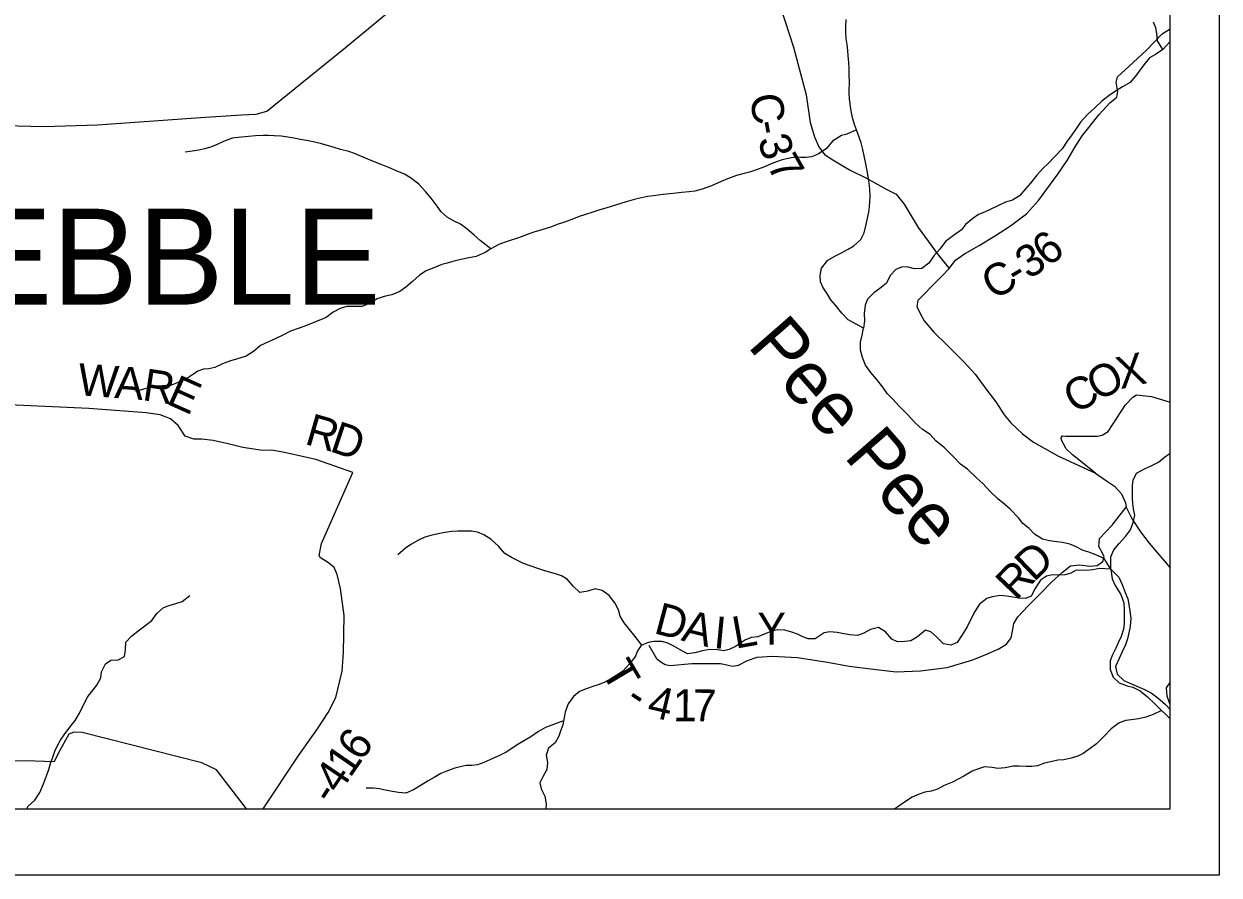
# Model space of a CAD drawing. Extents: x 0 to 34, y 0 to 22.
# Drawn here: x 6.965 to 9.087, y 13.882 to 15.393 of the extents above; entities that cross this region are included whole.
import ezdxf

# ---------------------------------------------------------------- set-up
doc = ezdxf.new("R2010")
doc.units = 0
for name, color, linetype in [('Default', 7, 'Continuous'), ('GM_X_County_Road', 7, 'Continuous'), ('GM_X_County_Road_Text', 7, 'Continuous'), ('GM_X_Major_River', 7, 'Continuous'), ('GM_X_Major_River_Text', 7, 'Continuous'), ('GM_X_Minor_Lake', 7, 'Continuous'), ('GM_X_Minor_River', 7, 'Continuous'), ('GM_X_Township_Road', 7, 'Continuous'), ('GM_X_Township_Road_Text', 7, 'Continuous'), ('GM_X_Township_Text', 7, 'Continuous'), ('SH_Cut_Line', 7, 'Continuous')]:
    doc.layers.add(name, color=color, linetype=linetype)

msp = doc.modelspace()

# ---------------------------------------------------------------- linework, layer by layer
at = {"layer": 'Default'}
msp.add_lwpolyline([(9.087, 13.8822), (2.1062, 13.8822), (2.1062, 20.9054), (9.087, 20.9054)], close=True, dxfattribs=at)
msp.add_lwpolyline([(4.485, 14), (9, 14), (9, 18.8941)], dxfattribs=at)
at = {"layer": 'GM_X_County_Road'}
for points in [[(8.3082, 15.4233), (8.3311, 15.3523), (8.3536, 15.2672), (8.361, 15.2182), (8.3686, 15.1927), (8.3765, 15.1749), (8.3863, 15.1616), (8.4011, 15.152), (8.4306, 15.1341), (8.4598, 15.1203), (8.4969, 15.0993), (8.5136, 15.091), (8.5276, 15.0734), (8.5529, 15.032), (8.5884, 14.9837), (8.6076, 14.959)], [(8.6076, 14.959), (8.6187, 14.9737), (8.6351, 14.9854), (8.6609, 15.0002), (8.6902, 15.0175), (8.7168, 15.0349), (8.7453, 15.0561), (8.7663, 15.0799), (8.8006, 15.1265), (8.817, 15.1508), (8.8315, 15.1754), (8.8437, 15.1947), (8.8741, 15.2326), (8.8928, 15.2531), (8.8993, 15.2587), (8.9057, 15.2636), (8.9073, 15.2739), (8.9062, 15.2796), (8.9043, 15.2902), (8.9066, 15.2993), (8.9268, 15.3175), (8.9584, 15.347), (8.9862, 15.3758), (9, 15.3849)], [(8.6076, 14.959), (8.5955, 14.9461), (8.5764, 14.9272), (8.5639, 14.9143), (8.5521, 14.9026), (8.5505, 14.8916), (8.5554, 14.8802), (8.5633, 14.8661), (8.5807, 14.8463), (8.6034, 14.8238), (8.6344, 14.7926), (8.6537, 14.7717), (8.6745, 14.7431), (8.6908, 14.7222), (8.7055, 14.6994), (8.7172, 14.6849), (8.738, 14.6655), (8.7577, 14.651), (8.8005, 14.6266), (8.8676, 14.5957), (8.8872, 14.5821), (8.9011, 14.5728), (8.9139, 14.5593), (8.9209, 14.5433), (8.922, 14.5357), (8.9325, 14.5139), (8.9473, 14.4914), (8.9629, 14.4716), (9, 14.4278)]]:
    msp.add_lwpolyline(points, dxfattribs=at)
at = {"layer": 'GM_X_Major_River'}
for points in [[(8.4556, 14.8532), (8.4283, 14.8683), (8.417, 14.8801), (8.4057, 14.8943), (8.3978, 14.9038), (8.3915, 14.9137), (8.3832, 14.9259), (8.3791, 14.9355), (8.3788, 14.9465), (8.3812, 14.9597), (8.3923, 14.9737), (8.4057, 14.9816), (8.4152, 14.9861), (8.4282, 14.9936), (8.4381, 14.9996), (8.4511, 15.0105), (8.4569, 15.0222), (8.46, 15.037), (8.4624, 15.0484), (8.4648, 15.059), (8.466, 15.0685), (8.4668, 15.078), (8.4673, 15.0875), (8.467, 15.1004), (8.4648, 15.1145), (8.463, 15.1259), (8.4612, 15.1354), (8.459, 15.1479), (8.4568, 15.1593), (8.4546, 15.1704), (8.4513, 15.1825), (8.448, 15.1924), (8.4431, 15.2054), (8.4398, 15.2149), (8.4364, 15.2248), (8.4342, 15.2354), (8.4324, 15.2468), (8.4306, 15.2605), (8.4303, 15.2719), (8.4305, 15.2917), (8.4302, 15.3019), (8.4299, 15.3141), (8.4296, 15.3251), (8.4286, 15.3365), (8.4275, 15.3464), (8.4265, 15.357), (8.425, 15.3677), (8.424, 15.3783), (8.424, 15.3889), (8.4245, 15.4011)], [(8.8949, 14.4256), (8.8827, 14.4441), (8.8684, 14.4506), (8.8559, 14.4556), (8.8456, 14.4587), (8.832, 14.4656), (8.8218, 14.4698), (8.8089, 14.4725), (8.7991, 14.4741), (8.7858, 14.4757), (8.7733, 14.4784), (8.7593, 14.4876), (8.7499, 14.4975), (8.7386, 14.5063), (8.731, 14.5162), (8.7163, 14.5318), (8.7065, 14.5402), (8.694, 14.5502), (8.6797, 14.5639), (8.6673, 14.5772), (8.6567, 14.5872), (8.6401, 14.6028), (8.6276, 14.612), (8.6152, 14.625), (8.5993, 14.641), (8.5838, 14.6532), (8.574, 14.6643), (8.5604, 14.6734), (8.5472, 14.6849), (8.5337, 14.7001), (8.5189, 14.7146), (8.5076, 14.7272), (8.4974, 14.7372), (8.4899, 14.7486), (8.4786, 14.7627), (8.4684, 14.7745), (8.459, 14.7878), (8.4538, 14.8012), (8.4501, 14.8141), (8.4501, 14.8281), (8.4532, 14.8407), (8.4556, 14.8532)], [(8.8949, 14.4256), (8.897, 14.4083), (8.9026, 14.3962), (8.9127, 14.3805), (8.9176, 14.3653), (8.9183, 14.3524), (8.9182, 14.3289), (8.9173, 14.319), (8.9131, 14.3061), (8.9077, 14.2947), (8.9035, 14.2853), (8.8978, 14.2731), (8.8935, 14.2625), (8.8935, 14.2473), (8.8987, 14.2336), (8.9096, 14.2237), (8.9236, 14.2183), (8.9339, 14.2156), (8.9471, 14.2095), (8.9599, 14.1988), (8.9724, 14.187), (8.9815, 14.1774), (8.9935, 14.166), (9, 14.1598)], [(8.8949, 14.4256), (8.9087, 14.4109), (8.9147, 14.3984), (8.9203, 14.3839), (8.9248, 14.3729), (8.9267, 14.3626), (8.9285, 14.3505), (8.93, 14.3383), (8.9291, 14.3235), (8.9268, 14.3121), (8.9241, 14.3019), (8.9206, 14.2913), (8.9149, 14.2784), (8.9095, 14.2666), (8.903, 14.2526), (8.9059, 14.2389), (8.918, 14.2279), (8.9316, 14.2217), (8.9449, 14.216), (8.9547, 14.2117), (8.9664, 14.2056), (8.9781, 14.1972), (8.9917, 14.185), (9, 14.1763)]]:
    msp.add_lwpolyline(points, dxfattribs=at)
at = {"layer": 'GM_X_Minor_Lake'}
msp.add_lwpolyline([(8.8949, 14.4256), (8.8827, 14.4441), (8.8684, 14.4506), (8.8559, 14.4556), (8.8456, 14.4587), (8.832, 14.4656), (8.8218, 14.4698), (8.8089, 14.4725), (8.7991, 14.4741), (8.7858, 14.4757), (8.7733, 14.4784), (8.7593, 14.4876), (8.7499, 14.4975), (8.7386, 14.5063), (8.731, 14.5162), (8.7163, 14.5318), (8.7065, 14.5402), (8.694, 14.5502), (8.6797, 14.5639), (8.6673, 14.5772), (8.6567, 14.5872), (8.6401, 14.6028), (8.6276, 14.612), (8.6152, 14.625), (8.5993, 14.641), (8.5838, 14.6532), (8.574, 14.6643), (8.5604, 14.6734), (8.5472, 14.6849), (8.5337, 14.7001), (8.5189, 14.7146), (8.5076, 14.7272), (8.4974, 14.7372), (8.4899, 14.7486), (8.4786, 14.7627), (8.4684, 14.7745), (8.459, 14.7878), (8.4538, 14.8012), (8.4501, 14.8141), (8.4501, 14.8281), (8.4532, 14.8407), (8.4556, 14.8532)], dxfattribs=at)
at = {"layer": 'GM_X_Minor_River'}
msp.add_line((7.8918, 14.0086), (7.8916, 14), dxfattribs=at)
for points in [[(8.9869, 15.3482), (8.9777, 15.3633), (8.9764, 15.3766), (8.9744, 15.3864), (8.9705, 15.3966)], [(9, 15.3624), (8.9993, 15.3616), (8.9869, 15.3482), (8.9741, 15.3393), (8.9635, 15.3332), (8.9556, 15.3236), (8.9481, 15.3137), (8.9402, 15.3029), (8.9289, 15.2896), (8.9157, 15.2814)], [(8.9157, 15.2814), (8.9029, 15.2737), (8.8919, 15.266), (8.8787, 15.256), (8.867, 15.2449), (8.8531, 15.2326), (8.8407, 15.2192), (8.8336, 15.2085), (8.8253, 15.1963), (8.8174, 15.1852), (8.8084, 15.1718), (8.7956, 15.1577), (8.7836, 15.1454), (8.7734, 15.1362), (8.7636, 15.1247), (8.752, 15.1109), (8.7437, 15.101), (8.7328, 15.088), (8.7204, 15.0802), (8.7079, 15.0771), (8.692, 15.069), (8.6814, 15.0647), (8.6704, 15.0593), (8.6598, 15.055), (8.6496, 15.0481), (8.6368, 15.0373), (8.6297, 15.0277), (8.6153, 15.0177), (8.6014, 15.007), (8.5909, 14.9936), (8.5803, 14.9817), (8.5713, 14.9687), (8.5593, 14.9591), (8.5464, 14.9586), (8.5326, 14.9619), (8.5232, 14.9614), (8.5129, 14.9575), (8.5028, 14.9468), (8.4964, 14.9331), (8.4848, 14.9235), (8.4742, 14.9158), (8.4625, 14.905), (8.4588, 14.894), (8.4567, 14.8791), (8.4575, 14.8662), (8.4556, 14.8532)], [(8.4431, 15.2054), (8.4258, 15.1977), (8.4163, 15.195), (8.4004, 15.185), (8.3899, 15.1723), (8.3748, 15.1623), (8.3631, 15.1573), (8.3536, 15.156), (8.3441, 15.1563), (8.3339, 15.1566), (8.3191, 15.1538), (8.3096, 15.1514), (8.2944, 15.146), (8.2797, 15.1394), (8.2638, 15.1335), (8.2532, 15.13), (8.2437, 15.128), (8.2301, 15.1241), (8.2142, 15.1186), (8.2028, 15.1136), (8.1854, 15.1062), (8.1691, 15.1), (8.1559, 15.0964), (8.146, 15.0952), (8.1324, 15.0939), (8.1229, 15.0931), (8.1119, 15.0918), (8.0997, 15.0906), (8.0819, 15.0881), (8.0717, 15.0869), (8.0614, 15.0849), (8.0508, 15.0825), (8.0341, 15.0774), (8.0167, 15.0719), (7.9982, 15.0664), (7.9872, 15.0633), (7.9747, 15.059), (7.9603, 15.0543), (7.9508, 15.0516), (7.9406, 15.0473), (7.9243, 15.0414), (7.9118, 15.0375), (7.9016, 15.0332), (7.8846, 15.0278), (7.8702, 15.0235), (7.86, 15.0199), (7.8497, 15.016), (7.8391, 15.0125), (7.8282, 15.0086), (7.8176, 15.0051), (7.8077, 15.0016), (7.7937, 14.9939), (7.7835, 14.9873), (7.768, 14.9807), (7.7517, 14.9775), (7.7381, 14.9747), (7.7263, 14.9716), (7.7165, 14.9688), (7.707, 14.9661), (7.6926, 14.9606), (7.679, 14.9548), (7.6673, 14.9475), (7.6549, 14.9363), (7.6428, 14.926), (7.6322, 14.9183), (7.6179, 14.9124), (7.6042, 14.9097), (7.5917, 14.9054), (7.5781, 14.8969), (7.5645, 14.8914), (7.5523, 14.8917), (7.5379, 14.8916), (7.5265, 14.888), (7.5137, 14.8818), (7.5012, 14.8722)], [(7.7937, 14.9939), (7.775, 15.0089), (7.7643, 15.0186), (7.7513, 15.0295), (7.7398, 15.0378), (7.7287, 15.0433), (7.7165, 15.0501), (7.7054, 15.0598), (7.6985, 15.0696), (7.6881, 15.084), (7.6778, 15.0956), (7.6659, 15.1088), (7.6514, 15.12), (7.6407, 15.1264), (7.6273, 15.132), (7.614, 15.1379), (7.5991, 15.1438), (7.5854, 15.149), (7.5755, 15.1535), (7.5519, 15.1631), (7.5416, 15.1668), (7.5271, 15.1705), (7.5153, 15.1738), (7.5039, 15.1775), (7.4932, 15.1804), (7.4811, 15.1833), (7.4662, 15.1862), (7.4556, 15.1884), (7.4438, 15.1906), (7.4335, 15.1924), (7.4217, 15.1938), (7.4088, 15.1944), (7.3989, 15.1951), (7.3894, 15.195), (7.3761, 15.1945), (7.3632, 15.1936), (7.345, 15.1919), (7.3344, 15.1903), (7.3193, 15.1848), (7.3068, 15.179), (7.2958, 15.1743), (7.286, 15.1716), (7.275, 15.1692), (7.2636, 15.1676), (7.2511, 15.1659)], [(7.5012, 14.8722), (7.4636, 14.8568), (7.4515, 14.8529), (7.4382, 14.8479), (7.4242, 14.841), (7.411, 14.8341), (7.3992, 14.8291), (7.3849, 14.8222), (7.3724, 14.8119), (7.3595, 14.8035), (7.3421, 14.7984), (7.3315, 14.795), (7.3175, 14.79), (7.3035, 14.7831), (7.2932, 14.7811), (7.2834, 14.7803), (7.2732, 14.7768), (7.2588, 14.7669), (7.249, 14.7623), (7.2368, 14.7561), (7.224, 14.7508), (7.2099, 14.7507), (7.1963, 14.7502), (7.1811, 14.746), (7.1713, 14.7429), (7.1618, 14.7413)], [(8.8949, 14.4256), (8.895, 14.4474), (8.9003, 14.4596), (8.9093, 14.471), (8.9206, 14.4836), (8.9297, 14.4954), (8.9346, 14.508), (8.9372, 14.5213), (8.9352, 14.5323), (8.934, 14.5417), (8.9332, 14.5512), (8.9332, 14.5645), (8.9335, 14.574), (8.9342, 14.5835), (8.9402, 14.5957), (8.9546, 14.6037), (8.9652, 14.608), (8.9796, 14.6156), (8.9898, 14.6244), (9, 14.6312)], [(8.062, 14.2907), (8.0502, 14.3059), (8.0403, 14.318), (8.0304, 14.3298), (8.0235, 14.3422), (8.0204, 14.3532), (8.0139, 14.3657), (8.004, 14.3786), (7.9914, 14.3873), (7.9793, 14.3906), (7.966, 14.386), (7.9516, 14.384), (7.9406, 14.3946), (7.9295, 14.4074), (7.9192, 14.4135), (7.9086, 14.4168), (7.898, 14.4202), (7.8881, 14.4232), (7.8774, 14.4265), (7.8638, 14.431), (7.8516, 14.4355), (7.841, 14.4408), (7.8315, 14.4456), (7.8189, 14.4532), (7.8075, 14.466), (7.7938, 14.4789), (7.7816, 14.4864), (7.7698, 14.4913), (7.7592, 14.4927), (7.7463, 14.4927), (7.7353, 14.4926), (7.7247, 14.4925), (7.7125, 14.4906), (7.7, 14.4882), (7.6872, 14.4851), (7.6765, 14.482), (7.6652, 14.4771), (7.6519, 14.4694), (7.6421, 14.4625), (7.6285, 14.451)], [(8.8949, 14.4256), (8.8754, 14.4268), (8.8621, 14.4244), (8.8523, 14.4229), (8.8333, 14.4235), (8.8235, 14.4185), (8.8136, 14.4154), (8.8007, 14.4146), (8.7905, 14.4153), (8.7806, 14.413), (8.77, 14.4061), (8.7602, 14.3909), (8.7531, 14.3775), (8.7433, 14.3733), (8.7315, 14.374), (8.7205, 14.3755), (8.7102, 14.3777), (8.6981, 14.3784), (8.6841, 14.376), (8.6746, 14.3733), (8.6617, 14.363), (8.6531, 14.3501), (8.6463, 14.3364), (8.6399, 14.3227), (8.6309, 14.3086), (8.6218, 14.2952), (8.6105, 14.2902), (8.5976, 14.2928), (8.585, 14.3053), (8.5751, 14.314), (8.5656, 14.317), (8.5516, 14.3055), (8.5399, 14.2982), (8.5289, 14.2967), (8.516, 14.2966), (8.5061, 14.3011), (8.4947, 14.3143), (8.4821, 14.3218), (8.4681, 14.318), (8.456, 14.3115), (8.445, 14.3076), (8.4314, 14.3087), (8.4207, 14.3105), (8.4086, 14.3131), (8.3957, 14.3142), (8.3855, 14.3122), (8.3696, 14.3015), (8.3574, 14.3015), (8.3479, 14.3052), (8.3381, 14.3097), (8.3282, 14.3138), (8.316, 14.3168), (8.3031, 14.3175), (8.2937, 14.3156), (8.2823, 14.3113), (8.2679, 14.3055), (8.2569, 14.304), (8.2459, 14.2997), (8.2285, 14.2879), (8.2172, 14.2825), (8.2077, 14.2806), (8.196, 14.282), (8.1827, 14.2827), (8.1694, 14.2804), (8.1561, 14.2769), (8.1433, 14.2753), (8.1311, 14.2813), (8.1185, 14.2884), (8.1079, 14.2937), (8.0973, 14.2967), (8.0832, 14.297), (8.073, 14.2954), (8.0605, 14.29), (8.0545, 14.2805), (8.0504, 14.271), (8.0409, 14.2581), (8.0273, 14.2436), (8.0175, 14.2371), (8.0069, 14.2305), (7.9948, 14.2244), (7.9842, 14.2198), (7.9747, 14.2171), (7.9649, 14.2132), (7.9513, 14.2079), (7.9403, 14.1995), (7.9313, 14.1861), (7.9256, 14.1713), (7.9238, 14.1618), (7.9216, 14.1492), (7.9182, 14.1397), (7.9148, 14.1291), (7.908, 14.1173), (7.896, 14.1074), (7.8922, 14.0952), (7.8942, 14.0823), (7.8935, 14.0694), (7.8859, 14.0568), (7.8807, 14.0458), (7.883, 14.0355), (7.8899, 14.0223), (7.8918, 14.0086)], [(6.9706, 14), (6.9717, 14.0039), (6.9842, 14.0153), (6.9928, 14.0287), (6.9992, 14.0443), (7.0048, 14.0587), (7.0086, 14.0697), (7.0119, 14.0804), (7.0161, 14.0918), (7.0198, 14.1021), (7.0243, 14.112), (7.0296, 14.1215), (7.036, 14.131), (7.0462, 14.1447), (7.0556, 14.1569), (7.0635, 14.1699), (7.077, 14.1973), (7.0853, 14.2079), (7.0944, 14.2194), (7.1015, 14.2323), (7.1026, 14.243), (7.1094, 14.257), (7.1192, 14.2635), (7.1317, 14.2644), (7.1431, 14.2705), (7.1449, 14.2823), (7.1456, 14.2959), (7.1562, 14.307), (7.1698, 14.3177), (7.1796, 14.325), (7.1917, 14.3341), (7.2004, 14.3467), (7.2121, 14.357), (7.2219, 14.3609), (7.2325, 14.3636), (7.2454, 14.3678), (7.259, 14.3785)], [(9, 14.1851), (8.999, 14.1879), (8.9948, 14.2), (8.9936, 14.2148), (9, 14.2239)], [(8.9847, 14.1744), (8.9702, 14.1676), (8.957, 14.1626), (8.9437, 14.1595), (8.9308, 14.1579), (8.9214, 14.1567), (8.9096, 14.1525), (8.8956, 14.1418), (8.8828, 14.1288), (8.8696, 14.1151), (8.8582, 14.1067), (8.8458, 14.0979), (8.8359, 14.0933), (8.8242, 14.0898), (8.8113, 14.0871), (8.8007, 14.0862), (8.7905, 14.0839), (8.7772, 14.0808), (8.7643, 14.0762), (8.7545, 14.075), (8.7446, 14.0753), (8.7321, 14.0756), (8.7215, 14.0756), (8.7071, 14.0725), (8.6942, 14.0713), (8.6843, 14.0735), (8.6706, 14.0742), (8.66, 14.0707), (8.6483, 14.0665), (8.6339, 14.0577), (8.6237, 14.0523), (8.6135, 14.0473), (8.5987, 14.0412), (8.587, 14.0346), (8.576, 14.0315), (8.5646, 14.0292), (8.5544, 14.0257), (8.5419, 14.0207), (8.5283, 14.0119), (8.5185, 14.0047), (8.511, 14)], [(7.9227, 14.1558), (7.8909, 14.1442), (7.8784, 14.1373), (7.8651, 14.1277), (7.8538, 14.1212), (7.839, 14.112), (7.822, 14.1013), (7.8092, 14.0944), (7.7921, 14.0867), (7.7815, 14.0821), (7.7702, 14.0782), (7.7603, 14.077), (7.7497, 14.0766), (7.7395, 14.0743), (7.73, 14.0723), (7.7167, 14.0673), (7.705, 14.0623), (7.6929, 14.0554), (7.6827, 14.0493), (7.6702, 14.0416), (7.6562, 14.0336), (7.6426, 14.0278), (7.6297, 14.0289), (7.6194, 14.0304), (7.6092, 14.0322), (7.5963, 14.0356), (7.5856, 14.0367), (7.5724, 14.0366)]]:
    msp.add_lwpolyline(points, dxfattribs=at)
at = {"layer": 'GM_X_Township_Road'}
for points in [[(6.9301, 15.213), (7.0006, 15.2113), (7.0955, 15.2144), (7.2781, 15.2272), (7.3513, 15.2322), (7.3771, 15.2329), (7.3958, 15.2386), (7.5354, 15.3513), (7.6309, 15.4303), (7.6545, 15.4481), (7.6647, 15.4575), (7.6724, 15.4765), (7.6889, 15.5467), (7.6996, 15.5797), (7.7035, 15.5918), (7.71, 15.6032), (7.7149, 15.6081), (7.7313, 15.6137), (7.8034, 15.626), (7.8406, 15.64), (7.8817, 15.6607), (7.9147, 15.68), (7.9395, 15.697)], [(7.3896, 14), (7.4514, 14.0934), (7.4858, 14.142), (7.5051, 14.171), (7.5188, 14.1975), (7.53, 14.2441), (7.5323, 14.2775), (7.5331, 14.3429), (7.5268, 14.3913), (7.521, 14.416), (7.5155, 14.4283), (7.5057, 14.4364), (7.491, 14.4453), (7.4888, 14.4499), (7.4928, 14.4708), (7.5487, 14.597), (7.4829, 14.6199), (7.4271, 14.6324), (7.4051, 14.6365), (7.3884, 14.636), (7.3535, 14.6414), (7.3296, 14.6474), (7.3004, 14.6538), (7.28, 14.6564), (7.2663, 14.6562), (7.2508, 14.6613), (7.2384, 14.6805), (7.2249, 14.6925), (7.2067, 14.6995), (7.1817, 14.7029), (7.0799, 14.7107), (6.6533, 14.7302)], [(8.8676, 14.5957), (8.8265, 14.6284), (8.8156, 14.6389), (8.8069, 14.6542), (8.8063, 14.6586), (8.8088, 14.6618), (8.8149, 14.6616), (8.8712, 14.6617), (8.8796, 14.663), (8.8901, 14.6698), (8.9206, 14.7174), (8.9336, 14.7307), (8.9401, 14.7349), (8.967, 14.7317), (9, 14.7216)], [(8.0744, 14.2907), (8.0882, 14.2669), (8.0954, 14.2611), (8.1033, 14.2561), (8.1124, 14.2544), (8.1508, 14.2581), (8.1755, 14.2578), (8.2017, 14.2579), (8.2127, 14.2554), (8.2233, 14.253), (8.2336, 14.2552), (8.2493, 14.2633), (8.2665, 14.2692), (8.2931, 14.2711), (8.3383, 14.2683), (8.3918, 14.2604), (8.4301, 14.253), (8.4779, 14.2471), (8.5136, 14.2428), (8.5566, 14.2446), (8.6042, 14.2508), (8.6499, 14.2646), (8.6729, 14.2739), (8.6946, 14.2835), (8.7096, 14.292), (8.7177, 14.3033), (8.7201, 14.3151), (8.7226, 14.3287), (8.7299, 14.3408), (8.748, 14.3603), (8.7707, 14.3829), (8.7892, 14.402), (8.8088, 14.42), (8.8234, 14.4312), (8.839, 14.4329), (8.8572, 14.4304), (8.8705, 14.4321), (8.8805, 14.4392), (8.8829, 14.4476), (8.8777, 14.4579), (8.8758, 14.4617), (8.8732, 14.4656), (8.8745, 14.4796), (8.8972, 14.5033), (8.922, 14.5357)], [(7.3599, 14), (7.3067, 14.0693), (7.2804, 14.0815), (7.0682, 14.1353), (7.0541, 14.1357), (7.0446, 14.1326), (7.0259, 14.0992), (7.0183, 14.0832), (6.9673, 14.0852), (6.8926, 14.0831)]]:
    msp.add_lwpolyline(points, dxfattribs=at)
at = {"layer": 'SH_Cut_Line'}
msp.add_lwpolyline([(2.2, 19.4329), (2.2, 14), (9, 14), (9, 18.8941), (8.8762, 18.9027), (8.0305, 18.9725), (6.8442, 19.0679), (6.226, 19.1161), (5.8337, 19.1499), (5.3224, 19.1939), (5.1554, 19.2083), (4.831, 19.2363), (4.7641, 19.2419), (3.1893, 19.3592), (2.7961, 19.3885)], close=True, dxfattribs=at)

# ---------------------------------------------------------------- texts
at = {"layer": 'GM_X_County_Road_Text'}
for s, rotation, p in [('C', 279.1126, (8.2532, 15.2658)), ('-', 280.5471, (8.2609, 15.2182)), ('3', 287.5196, (8.267, 15.1879)), ('7', 299.7714, (8.2828, 15.1424)), ('6', 37.2762, (8.7825, 14.9606)), ('3', 32.5698, (8.7488, 14.9389)), ('C', 30.6177, (8.6869, 14.9019)), ('-', 31.1572, (8.7276, 14.926))]:
    msp.add_text(s, height=0.0568, rotation=rotation, dxfattribs=at).set_placement(p)
at = {"layer": 'GM_X_Major_River_Text'}
msp.add_text('Pee Pee', height=0.0947, rotation=311.1108, dxfattribs=at).set_placement((8.2477, 14.8214))
at = {"layer": 'GM_X_Township_Road_Text'}
for s, rotation, p in [('X', 12.8726, (8.9117, 14.7447)), ('W', 355.777, (7.059, 14.7344)), ('A', 355.6024, (7.1246, 14.7295)), ('R', 351.3256, (7.1734, 14.7258)), ('O', 28.3346, (8.8715, 14.7224)), ('E', 335.8813, (7.2156, 14.7199)), ('C', 28.8469, (8.8308, 14.7)), ('R', 343.9206, (7.4614, 14.648)), ('D', 341.3381, (7.5056, 14.6353)), ('D', 43.8125, (8.758, 14.4013)), ('R', 46.3082, (8.7262, 14.3681)), ('D', 345.1615, (8.0813, 14.3122)), ('A', 345.971, (8.1304, 14.2991)), ('Y', 0.2477, (8.2674, 14.2912)), ('I', 354.5025, (8.188, 14.2855)), ('L', 10.2191, (8.2282, 14.2839)), ('T', 300.647, (7.9888, 14.2432)), ('-', 326.8861, (8.0299, 14.1863)), ('4', 346.6879, (8.069, 14.1652)), ('1', 359.8255, (8.1171, 14.1555)), ('7', 359.1413, (8.152, 14.1554)), ('6', 55.1725, (7.5637, 14.0821)), ('1', 55.4121, (7.5438, 14.0534)), ('4', 55.9289, (7.5243, 14.0245)), ('-', 56.4074, (7.5115, 14.0052))]:
    msp.add_text(s, height=0.0568, rotation=rotation, dxfattribs=at).set_placement(p)
at = {"layer": 'GM_X_Township_Text'}
msp.add_text('PEBBLE', height=0.17045, rotation=0, dxfattribs=at).set_placement((6.7107, 14.895))

doc.saveas('drawing.dxf')
